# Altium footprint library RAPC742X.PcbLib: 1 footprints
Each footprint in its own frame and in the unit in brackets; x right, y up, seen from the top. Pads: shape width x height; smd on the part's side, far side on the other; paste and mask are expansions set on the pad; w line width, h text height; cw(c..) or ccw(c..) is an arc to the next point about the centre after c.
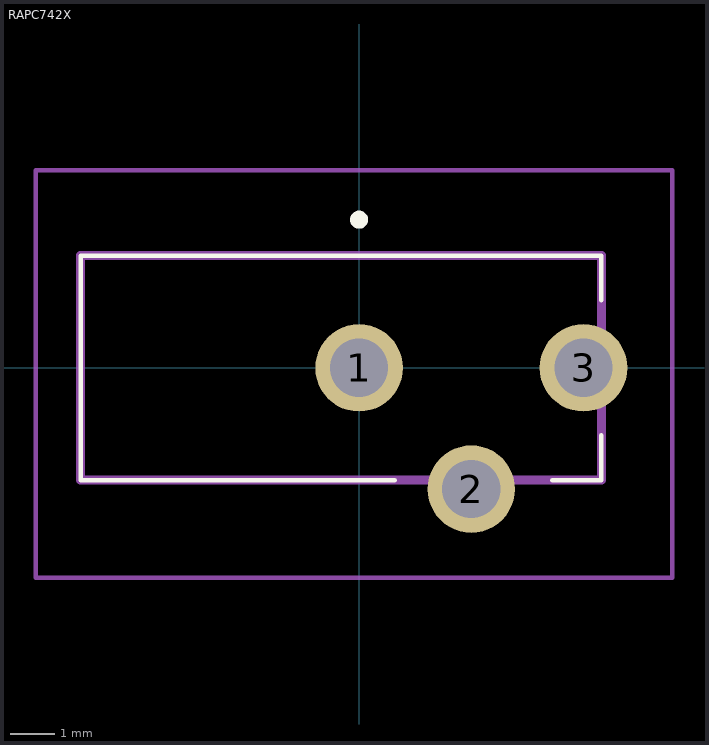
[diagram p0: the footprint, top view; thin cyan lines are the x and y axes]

## RAPC742X [mm]
pads (3):
  round 1.95 hole 1.3: 1(0,0) 2(2.5,-2.7) 3(5,0)
Top Overlay:
  lines w0.1: 0.8,-2.5 -6.2,-2.5 -6.2,2.5 5.4,2.5 5.4,1.5 ; 4.3,-2.5 5.4,-2.5 5.4,-1.5
  lines w0.2: -0.1,3.3 -0.1,3.3 ; -0.1,3.3 ccw(c0,3.3) 0.1,3.3 ; -0.1,3.3 cw(c0,3.3) 0.1,3.3 ; 0.1,3.3 0.1,3.3
Mechanical 15:
  lines w0.2: -6.2,-2.5 5.4,-2.5 5.4,2.5 -6.2,2.5 -6.2,-2.5
Mechanical 20:
  lines w0.1: -7.2,-4.675 6.975,-4.675 6.975,4.4 -7.2,4.4 -7.2,-4.675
